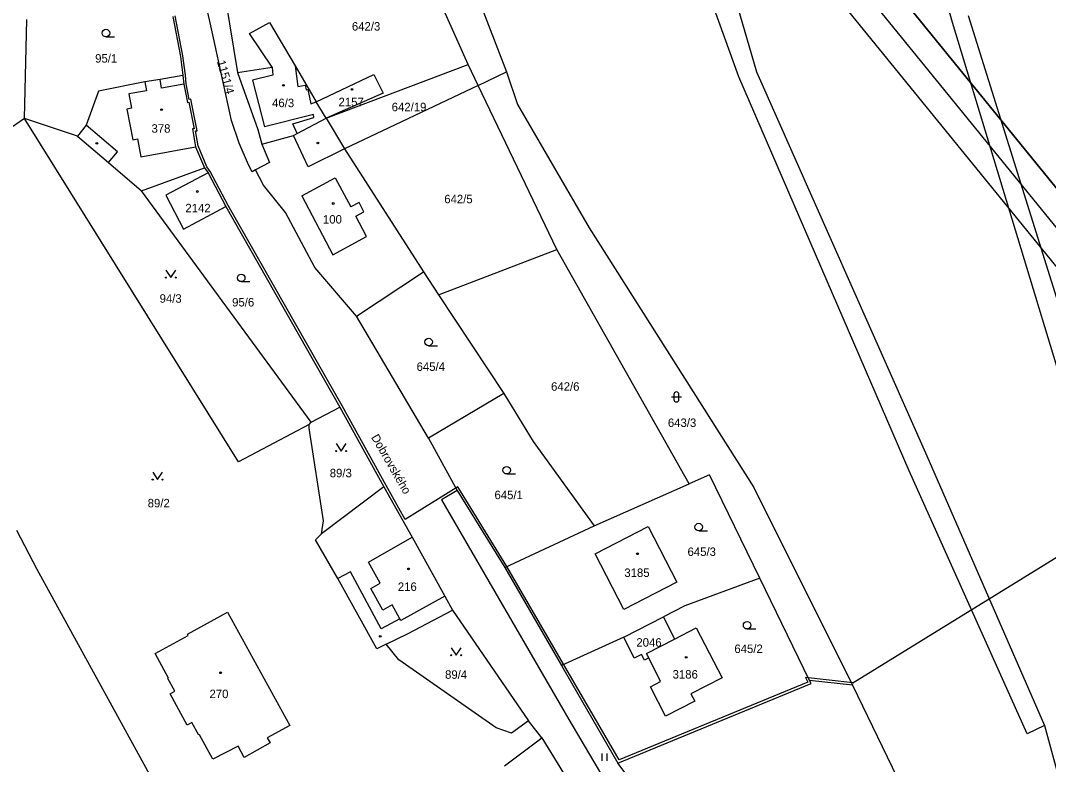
# Model space of a CAD drawing. Extents: x -866656 to -858817, y -1041816 to -1038653.
# Drawn here: x -865965.3 to -865759.2, y -1039768.1 to -1039618.8 of the extents above; entities that cross this region are included whole.
import ezdxf

# ---------------------------------------------------------------- set-up
doc = ezdxf.new("R2010")
doc.units = 0
for name, color, linetype in [('Hranice parcel', 7, 'Continuous'), ('Parcelní čísla', 7, 'Continuous'), ('Pop  PČ popisy', 7, 'Continuous'), ('tisk ramy', 7, 'Continuous'), ('Vnitřní kresba', 7, 'Continuous'), ('Značky budov', 7, 'Continuous'), ('Značky kultur', 7, 'Continuous')]:
    doc.layers.add(name, color=color, linetype=linetype)

msp = doc.modelspace()

# ---------------------------------------------------------------- linework, layer by layer
at = {"layer": 'Hranice parcel'}
for p, q in [((-865835.87, -1039567.01), (-865817.77, -1039629.15)), ((-865821.31, -1039630.13), (-865843.23, -1039569.42)), ((-865778.45, -1039619.21), (-865790.14, -1039576.93)), ((-865881.62, -1039593.19), (-865867.89, -1039629.16)), ((-865875.59, -1039627.64), (-865889.29, -1039596.77)), ((-865926.61, -1039622.34), (-865930.65, -1039604.31)), ((-865924.2, -1039614.57), (-865921.83, -1039629.29)), ((-865934.76, -1039618.02), (-865933.22, -1039626.03)), ((-865746.86, -1039708.89), (-865775.27, -1039617.9)), ((-865964.5, -1039638.5), (-865964.04, -1039618.62)), ((-865919.37, -1039621.43), (-865915.38, -1039619.24)), ((-865915.38, -1039619.24), (-865910.26, -1039627.96)), ((-865751.35, -1039708.82), (-865778.45, -1039619.21)), ((-865923, -1039638.89), (-865926.61, -1039622.34)), ((-865914.84, -1039628.21), (-865919.37, -1039621.43)), ((-865933.22, -1039626.03), (-865932.76, -1039629.87)), ((-865921.83, -1039629.29), (-865914.84, -1039628.21)), ((-865910.26, -1039627.96), (-865906.03, -1039635.13)), ((-865904.06, -1039638.42), (-865875.59, -1039627.64)), ((-865873.57, -1039631.86), (-865875.59, -1039627.64)), ((-865937.34, -1039630.65), (-865940.35, -1039631.16)), ((-865932.76, -1039629.87), (-865937.34, -1039630.65)), ((-865932.76, -1039629.87), (-865932.57, -1039631.61)), ((-865921.83, -1039629.29), (-865917.72, -1039640.71)), ((-865906.03, -1039635.13), (-865894.5, -1039629.64)), ((-865894.5, -1039629.64), (-865892.58, -1039633.42)), ((-865873.57, -1039631.86), (-865867.89, -1039629.16)), ((-865867.89, -1039629.16), (-865865.65, -1039635.66)), ((-865787.17, -1039709.19), (-865821.31, -1039630.13)), ((-865817.77, -1039629.15), (-865783.64, -1039706.2)), ((-865940.35, -1039631.16), (-865949.64, -1039633.02)), ((-865932.57, -1039631.61), (-865931.85, -1039635.26)), ((-865873.57, -1039631.86), (-865900.35, -1039644.61)), ((-865857.79, -1039664.79), (-865873.57, -1039631.86)), ((-865949.64, -1039633.02), (-865952.15, -1039639.81)), ((-865892.58, -1039633.42), (-865904.06, -1039638.42)), ((-865931.85, -1039635.26), (-865931.56, -1039635.2)), ((-865931.56, -1039635.2), (-865930.51, -1039640.54)), ((-865904.06, -1039638.42), (-865906.03, -1039635.13)), ((-865865.65, -1039635.66), (-865851.31, -1039660.42)), ((-865964.5, -1039638.5), (-865979.95, -1039649.17)), ((-865953.89, -1039642.01), (-865964.5, -1039638.5)), ((-865921.6, -1039707.4), (-865964.5, -1039638.5)), ((-865921.46, -1039643.46), (-865923, -1039638.89)), ((-865909.83, -1039641.49), (-865904.06, -1039638.42)), ((-865904.06, -1039638.42), (-865900.35, -1039644.61)), ((-865952.15, -1039639.81), (-865953.89, -1039642.01)), ((-865930.51, -1039640.54), (-865930.81, -1039640.59)), ((-865930.81, -1039640.59), (-865930.2, -1039644.15)), ((-865917.72, -1039640.71), (-865916.93, -1039643.68)), ((-865953.89, -1039642.01), (-865947.68, -1039647.31)), ((-865916.93, -1039643.68), (-865910.6, -1039641.9)), ((-865910.6, -1039641.9), (-865909.83, -1039641.49)), ((-865930.2, -1039644.15), (-865928.42, -1039648.42)), ((-865919.57, -1039647.82), (-865921.46, -1039643.46)), ((-865916.93, -1039643.68), (-865915.39, -1039647.33)), ((-865900.35, -1039644.61), (-865884.51, -1039669.29)), ((-865947.68, -1039647.31), (-865941.06, -1039653.04)), ((-865915.39, -1039647.33), (-865918.17, -1039648.83)), ((-865941.06, -1039653.04), (-865928.42, -1039648.42)), ((-865927.68, -1039649.42), (-865936.16, -1039653.91)), ((-865928.42, -1039648.42), (-865927.68, -1039649.42)), ((-865927.68, -1039649.42), (-865924.11, -1039656.17)), ((-865918.88, -1039649.21), (-865919.57, -1039647.82)), ((-865918.17, -1039648.83), (-865918.88, -1039649.21)), ((-865916.61, -1039651.9), (-865918.17, -1039648.83)), ((-865907.06, -1039699.41), (-865941.06, -1039653.04)), ((-865912.15, -1039657.34), (-865916.61, -1039651.9)), ((-865936.16, -1039653.91), (-865932.62, -1039660.67)), ((-865932.62, -1039660.67), (-865924.11, -1039656.17)), ((-865924.11, -1039656.17), (-865901.26, -1039696.41)), ((-865906.27, -1039668.39), (-865912.15, -1039657.34)), ((-865851.31, -1039660.42), (-865818.32, -1039712.56)), ((-865881.49, -1039673.85), (-865857.79, -1039664.79)), ((-865831.23, -1039711.8), (-865857.79, -1039664.79)), ((-865897.97, -1039678.16), (-865906.27, -1039668.39)), ((-865897.97, -1039678.16), (-865884.51, -1039669.29)), ((-865884.51, -1039669.29), (-865881.49, -1039673.85)), ((-865881.49, -1039673.85), (-865868.4, -1039693.64)), ((-865883.5, -1039702.66), (-865897.97, -1039678.16)), ((-865868.4, -1039693.64), (-865883.5, -1039702.66)), ((-865868.4, -1039693.64), (-865862.5, -1039703.28)), ((-865907.06, -1039699.41), (-865901.26, -1039696.41)), ((-865901.26, -1039696.41), (-865892.44, -1039712.4)), ((-865907.44, -1039699.86), (-865921.6, -1039707.4)), ((-865907.45, -1039700.64), (-865907.44, -1039699.86)), ((-865904.57, -1039719.25), (-865907.45, -1039700.64)), ((-865907.44, -1039699.86), (-865907.06, -1039699.41)), ((-865883.5, -1039702.66), (-865877.76, -1039713.11)), ((-865862.5, -1039703.28), (-865850.28, -1039720.24)), ((-865783.64, -1039706.2), (-865760, -1039760.31)), ((-865763.49, -1039761.95), (-865787.17, -1039709.19)), ((-865827.18, -1039710), (-865831.23, -1039711.8)), ((-865817.11, -1039730.7), (-865827.18, -1039710)), ((-865892.44, -1039712.4), (-865904.95, -1039721.82)), ((-865892.44, -1039712.4), (-865886.77, -1039722.5)), ((-865877.76, -1039713.11), (-865880.91, -1039715.04)), ((-865877.76, -1039713.11), (-865868.22, -1039728.61)), ((-865850.28, -1039720.24), (-865831.23, -1039711.8)), ((-865818.32, -1039712.56), (-865798.51, -1039752.21)), ((-865880.91, -1039715.04), (-865855.38, -1039759.07)), ((-865904.95, -1039721.82), (-865904.57, -1039719.25)), ((-865966.09, -1039721.08), (-865962.04, -1039728.92)), ((-865868.22, -1039728.61), (-865850.28, -1039720.24)), ((-865850.09, -1039725.87), (-865839.47, -1039720.36)), ((-865839.47, -1039720.36), (-865833.7, -1039731.5)), ((-865906.19, -1039723), (-865904.95, -1039721.82)), ((-865901.67, -1039730.81), (-865906.19, -1039723)), ((-865886.77, -1039722.5), (-865880.24, -1039734.31)), ((-865844.35, -1039736.98), (-865850.09, -1039725.87)), ((-865962.04, -1039728.92), (-865937.68, -1039773.29)), ((-865868.22, -1039728.61), (-865856.88, -1039748.22)), ((-865893.89, -1039744.93), (-865901.67, -1039730.81)), ((-865833.7, -1039731.5), (-865844.35, -1039736.98)), ((-865817.11, -1039730.7), (-865832.11, -1039736.28)), ((-865807.11, -1039751.25), (-865817.11, -1039730.7)), ((-865880.24, -1039734.31), (-865878.7, -1039737.15)), ((-865931.83, -1039741.93), (-865923.83, -1039737.53)), ((-865923.83, -1039737.53), (-865911.32, -1039760.3)), ((-865887.69, -1039741.87), (-865878.7, -1039737.15)), ((-865878.7, -1039737.15), (-865863.48, -1039759.33)), ((-865832.11, -1039736.28), (-865836.37, -1039738.47)), ((-865844.37, -1039742.59), (-865836.37, -1039738.47)), ((-865836.37, -1039738.47), (-865834.18, -1039742.93)), ((-865931.69, -1039742.2), (-865931.83, -1039741.93)), ((-865892.01, -1039743.98), (-865887.69, -1039741.87)), ((-865834.18, -1039742.93), (-865829.83, -1039740.69)), ((-865829.83, -1039740.69), (-865824.66, -1039750.72)), ((-865938.32, -1039745.85), (-865931.69, -1039742.2)), ((-865892.01, -1039743.98), (-865893.89, -1039744.93)), ((-865889.44, -1039747.14), (-865892.01, -1039743.98)), ((-865844.37, -1039742.59), (-865856.88, -1039748.22)), ((-865842.3, -1039746.78), (-865844.37, -1039742.59)), ((-865839.8, -1039745.82), (-865834.18, -1039742.93)), ((-865935.63, -1039750.8), (-865938.32, -1039745.85)), ((-865840.79, -1039746.01), (-865842.3, -1039746.78)), ((-865840.2, -1039747.17), (-865840.79, -1039746.01)), ((-865839.34, -1039746.73), (-865839.8, -1039745.82)), ((-865869.95, -1039760.74), (-865889.44, -1039747.14)), ((-865856.88, -1039748.22), (-865845.53, -1039767.83)), ((-865839.34, -1039746.73), (-865840.2, -1039747.17)), ((-865836.97, -1039751.43), (-865839.34, -1039746.73)), ((-865935.76, -1039750.87), (-865935.63, -1039750.8)), ((-865934.38, -1039753.41), (-865935.76, -1039750.87)), ((-865845.53, -1039767.83), (-865806.8, -1039751.88)), ((-865839.03, -1039752.53), (-865836.97, -1039751.43)), ((-865824.66, -1039750.72), (-865830.91, -1039753.92)), ((-865798.51, -1039752.21), (-865807.11, -1039751.25)), ((-865806.8, -1039751.88), (-865807.11, -1039751.25)), ((-865798.51, -1039752.21), (-865779.36, -1039791.75)), ((-865935.3, -1039753.9), (-865934.38, -1039753.41)), ((-865931.87, -1039760.2), (-865935.3, -1039753.9)), ((-865835.99, -1039758.41), (-865839.03, -1039752.53)), ((-865830.91, -1039753.92), (-865830.13, -1039755.43)), ((-865830.13, -1039755.43), (-865835.99, -1039758.41)), ((-865930.96, -1039759.71), (-865931.87, -1039760.2)), ((-865929.58, -1039762.25), (-865930.96, -1039759.71)), ((-865911.32, -1039760.3), (-865915.86, -1039762.74)), ((-865863.48, -1039759.33), (-865866.85, -1039761.83)), ((-865860.81, -1039762.76), (-865863.48, -1039759.33)), ((-865855.38, -1039759.07), (-865846.06, -1039774.86)), ((-865760, -1039760.31), (-865763.49, -1039761.95)), ((-865760, -1039760.31), (-865755.41, -1039777.32)), ((-865929.44, -1039762.17), (-865929.58, -1039762.25)), ((-865926.72, -1039767.06), (-865929.44, -1039762.17)), ((-865915.86, -1039762.74), (-865915.27, -1039763.79)), ((-865866.85, -1039761.83), (-865869.95, -1039760.74)), ((-865868.31, -1039768.37), (-865860.81, -1039762.76)), ((-865860.81, -1039762.76), (-865854.06, -1039773.66)), ((-865921.67, -1039764.44), (-865926.72, -1039767.06)), ((-865920.44, -1039766.71), (-865921.67, -1039764.44)), ((-865915.27, -1039763.79), (-865920.44, -1039766.71)), ((-865843.66, -1039770.29), (-865845.53, -1039767.83))]:
    msp.add_line(p, q, dxfattribs=at)
at = {"layer": 'tisk ramy'}
for points in [[(-866268.65, -1039040.03), (-865473.6, -1040017.5), (-865243.2, -1039830.1), (-866038.25, -1038852.63)], [(-866038.97, -1038859.66), (-865250.23, -1039829.38), (-865472.87, -1040010.47), (-866261.62, -1039040.75)], [(-866254.59, -1039041.47), (-865601.5, -1039844.41), (-865386.61, -1039669.62), (-866039.7, -1038866.69)], [(-866039.7, -1038866.69), (-865386.61, -1039669.62), (-865601.5, -1039844.41), (-866254.59, -1039041.47)]]:
    msp.add_lwpolyline(points, close=True, dxfattribs=at)
at = {"layer": 'Vnitřní kresba'}
for p, q in [((-865932.73, -1039625.95), (-865934.27, -1039617.91)), ((-865932.26, -1039629.81), (-865932.73, -1039625.95)), ((-865914.84, -1039628.21), (-865914.7, -1039629.78)), ((-865910.26, -1039627.96), (-865909.74, -1039632.05)), ((-865937.03, -1039632.44), (-865937.34, -1039630.65)), ((-865932.08, -1039631.53), (-865932.26, -1039629.81)), ((-865914.7, -1039629.78), (-865918.77, -1039630.81)), ((-865918.77, -1039630.81), (-865916.4, -1039640.17)), ((-865940.35, -1039631.16), (-865940.04, -1039632.96)), ((-865932.57, -1039631.61), (-865937.03, -1039632.44)), ((-865931.46, -1039634.67), (-865932.08, -1039631.53)), ((-865909.74, -1039632.05), (-865908.24, -1039631.79)), ((-865908.24, -1039631.79), (-865908.03, -1039632.72)), ((-865908.03, -1039632.72), (-865907.73, -1039632.66)), ((-865907.73, -1039632.66), (-865907.09, -1039635.58)), ((-865940.04, -1039632.96), (-865943.58, -1039633.56)), ((-865943.58, -1039633.56), (-865943.03, -1039636.42)), ((-865931.17, -1039634.61), (-865931.46, -1039634.67)), ((-865929.92, -1039640.95), (-865931.17, -1039634.61)), ((-865943.03, -1039636.42), (-865943.99, -1039636.6)), ((-865943.99, -1039636.6), (-865942.8, -1039642.8)), ((-865907.09, -1039635.58), (-865906.03, -1039635.13)), ((-865906.56, -1039637.68), (-865916.4, -1039640.17)), ((-865910.74, -1039639.6), (-865906.48, -1039638.29)), ((-865906.48, -1039638.29), (-865906.56, -1039637.68)), ((-865945.87, -1039645.21), (-865952.15, -1039639.81)), ((-865930.23, -1039641), (-865929.92, -1039640.95)), ((-865929.72, -1039644.01), (-865930.23, -1039641)), ((-865909.83, -1039641.49), (-865910.74, -1039639.6)), ((-865942.8, -1039642.8), (-865941.84, -1039642.61)), ((-865941.84, -1039642.61), (-865941.16, -1039646.16)), ((-865907.62, -1039648.21), (-865910.6, -1039641.9)), ((-865947.68, -1039647.31), (-865945.87, -1039645.21)), ((-865941.16, -1039646.16), (-865930.2, -1039644.15)), ((-865927.98, -1039648.17), (-865929.72, -1039644.01)), ((-865900.35, -1039644.61), (-865907.62, -1039648.21)), ((-865927.26, -1039649.15), (-865927.98, -1039648.17)), ((-865923.67, -1039655.93), (-865927.26, -1039649.15)), ((-865908.89, -1039653.99), (-865902.21, -1039650.37)), ((-865902.21, -1039650.37), (-865899.05, -1039656.19)), ((-865908.89, -1039653.99), (-865902.71, -1039665.88)), ((-865897.42, -1039655.35), (-865899.05, -1039656.19)), ((-865896.45, -1039657.22), (-865897.42, -1039655.35)), ((-865900.82, -1039696.17), (-865923.67, -1039655.93)), ((-865898.08, -1039658.07), (-865896.45, -1039657.22)), ((-865895.96, -1039662.15), (-865898.08, -1039658.07)), ((-865902.71, -1039665.88), (-865895.96, -1039662.15)), ((-865798.45, -1039751.71), (-865696.09, -1039688.49)), ((-865892, -1039712.16), (-865900.82, -1039696.17)), ((-865888.2, -1039718.92), (-865892, -1039712.16)), ((-865877.6, -1039712.42), (-865888.2, -1039718.92)), ((-865867.79, -1039728.35), (-865877.6, -1039712.42)), ((-865895.53, -1039727.5), (-865886.77, -1039722.5)), ((-865893.19, -1039731.75), (-865895.53, -1039727.5)), ((-865899.16, -1039729.45), (-865901.67, -1039730.81)), ((-865892.99, -1039740.86), (-865899.16, -1039729.45)), ((-865856.45, -1039747.97), (-865867.79, -1039728.35)), ((-865895.07, -1039732.79), (-865893.19, -1039731.75)), ((-865892.67, -1039737.13), (-865895.07, -1039732.79)), ((-865880.24, -1039734.31), (-865889.06, -1039739.23)), ((-865890.79, -1039736.09), (-865892.67, -1039737.13)), ((-865889.24, -1039738.89), (-865890.79, -1039736.09)), ((-865889.24, -1039738.89), (-865892.99, -1039740.86)), ((-865889.06, -1039739.23), (-865889.24, -1039738.89)), ((-865845.32, -1039767.2), (-865856.45, -1039747.97)), ((-865807.48, -1039751.62), (-865845.32, -1039767.2)), ((-865798.45, -1039751.71), (-865807.96, -1039750.65)), ((-865807.96, -1039750.65), (-865807.48, -1039751.62))]:
    msp.add_line(p, q, dxfattribs=at)
at = {"layer": 'Značky budov'}
for centre in [(-865912.59, -1039631.85), (-865898.84, -1039632.66), (-865937.03, -1039636.73), (-865905.69, -1039643.41), (-865950, -1039643.49), (-865929.86, -1039653.15), (-865902.61, -1039655.56), (-865841.61, -1039725.83), (-865887.5, -1039728.86), (-865893.18, -1039742.4), (-865831.85, -1039746.6), (-865925.2, -1039749.7)]:
    msp.add_circle(centre, 0.175, dxfattribs=at)
at = {"layer": 'Značky kultur'}
for p, q in [((-865948.18, -1039622.1), (-865946.43, -1039622.1)), ((-865921.05, -1039671.23), (-865919.3, -1039671.23)), ((-865883.49, -1039684.09), (-865881.74, -1039684.09)), ((-865834.82, -1039694.36), (-865832.82, -1039694.36)), ((-865834.32, -1039693.86), (-865834.32, -1039694.86)), ((-865833.32, -1039694.86), (-865833.32, -1039693.86)), ((-865867.84, -1039709.82), (-865866.09, -1039709.82)), ((-865829.35, -1039721.22), (-865827.6, -1039721.22)), ((-865819.64, -1039740.92), (-865817.89, -1039740.92)), ((-865848.67, -1039767.4), (-865848.67, -1039765.9)), ((-865847.67, -1039767.4), (-865847.67, -1039765.9))]:
    msp.add_line(p, q, dxfattribs=at)
for points in [[(-865936.17, -1039668.91), (-865935.17, -1039670.41), (-865934.17, -1039668.91)], [(-865902.02, -1039703.73), (-865901.02, -1039705.23), (-865900.02, -1039703.73)], [(-865938.81, -1039709.43), (-865937.81, -1039710.93), (-865936.81, -1039709.43)], [(-865878.95, -1039744.68), (-865877.95, -1039746.18), (-865876.95, -1039744.68)]]:
    msp.add_lwpolyline(points, dxfattribs=at)
for centre, radius in [((-865948.18, -1039621.35), 0.75), ((-865921.05, -1039670.48), 0.75), ((-865936.17, -1039670.41), 0.1), ((-865934.17, -1039670.41), 0.1), ((-865883.49, -1039683.34), 0.75), ((-865902.02, -1039705.23), 0.1), ((-865900.02, -1039705.23), 0.1), ((-865867.84, -1039709.07), 0.75), ((-865938.81, -1039710.93), 0.1), ((-865936.81, -1039710.93), 0.1), ((-865829.35, -1039720.47), 0.75), ((-865819.64, -1039740.17), 0.75), ((-865878.95, -1039746.18), 0.1), ((-865876.95, -1039746.18), 0.1)]:
    msp.add_circle(centre, radius, dxfattribs=at)
for centre, start, end in [((-865833.82, -1039693.86), 0, 180), ((-865833.82, -1039694.86), 180, 359.9879)]:
    msp.add_arc(centre, 0.5, start, end, dxfattribs=at)

# ---------------------------------------------------------------- texts
at = {"layer": 'Parcelní čísla'}
for s, p in [('642/3', (-865898.87, -1039620.86)), ('95/1', (-865950.34, -1039627.29)), ('46/3', (-865914.87, -1039636.22)), ('2157', (-865901.55, -1039636.03)), ('642/19', (-865890.89, -1039637.04)), ('378', (-865939.04, -1039641.35)), ('2142', (-865932.25, -1039657.32)), ('642/5', (-865880.35, -1039655.51)), ('100', (-865904.67, -1039659.58)), ('94/3', (-865937.42, -1039675.46)), ('95/6', (-865922.88, -1039676.21)), ('645/4', (-865885.9, -1039689.14)), ('642/6', (-865858.94, -1039693.12)), ('643/3', (-865835.52, -1039700.39)), ('89/3', (-865903.31, -1039710.48)), ('645/1', (-865870.28, -1039714.87)), ('89/2', (-865939.81, -1039716.52)), ('645/3', (-865831.58, -1039726.27)), ('3185', (-865844.25, -1039730.48)), ('216', (-865889.66, -1039733.28)), ('2046', (-865841.84, -1039744.47)), ('645/2', (-865822.19, -1039745.74)), ('89/4', (-865880.19, -1039750.91)), ('3186', (-865834.57, -1039750.87)), ('270', (-865927.42, -1039754.79))]:
    msp.add_text(s, height=1.7, dxfattribs=at).set_placement(p)
msp.add_text('1151/4', height=1.7, rotation=286, dxfattribs=at).set_placement((-865925.95, -1039627.07))
at = {"layer": 'Pop  PČ popisy'}
msp.add_text('Dobrovského', height=1.7, rotation=300, dxfattribs=at).set_placement((-865895.07, -1039702.45))

doc.saveas('drawing.dxf')
